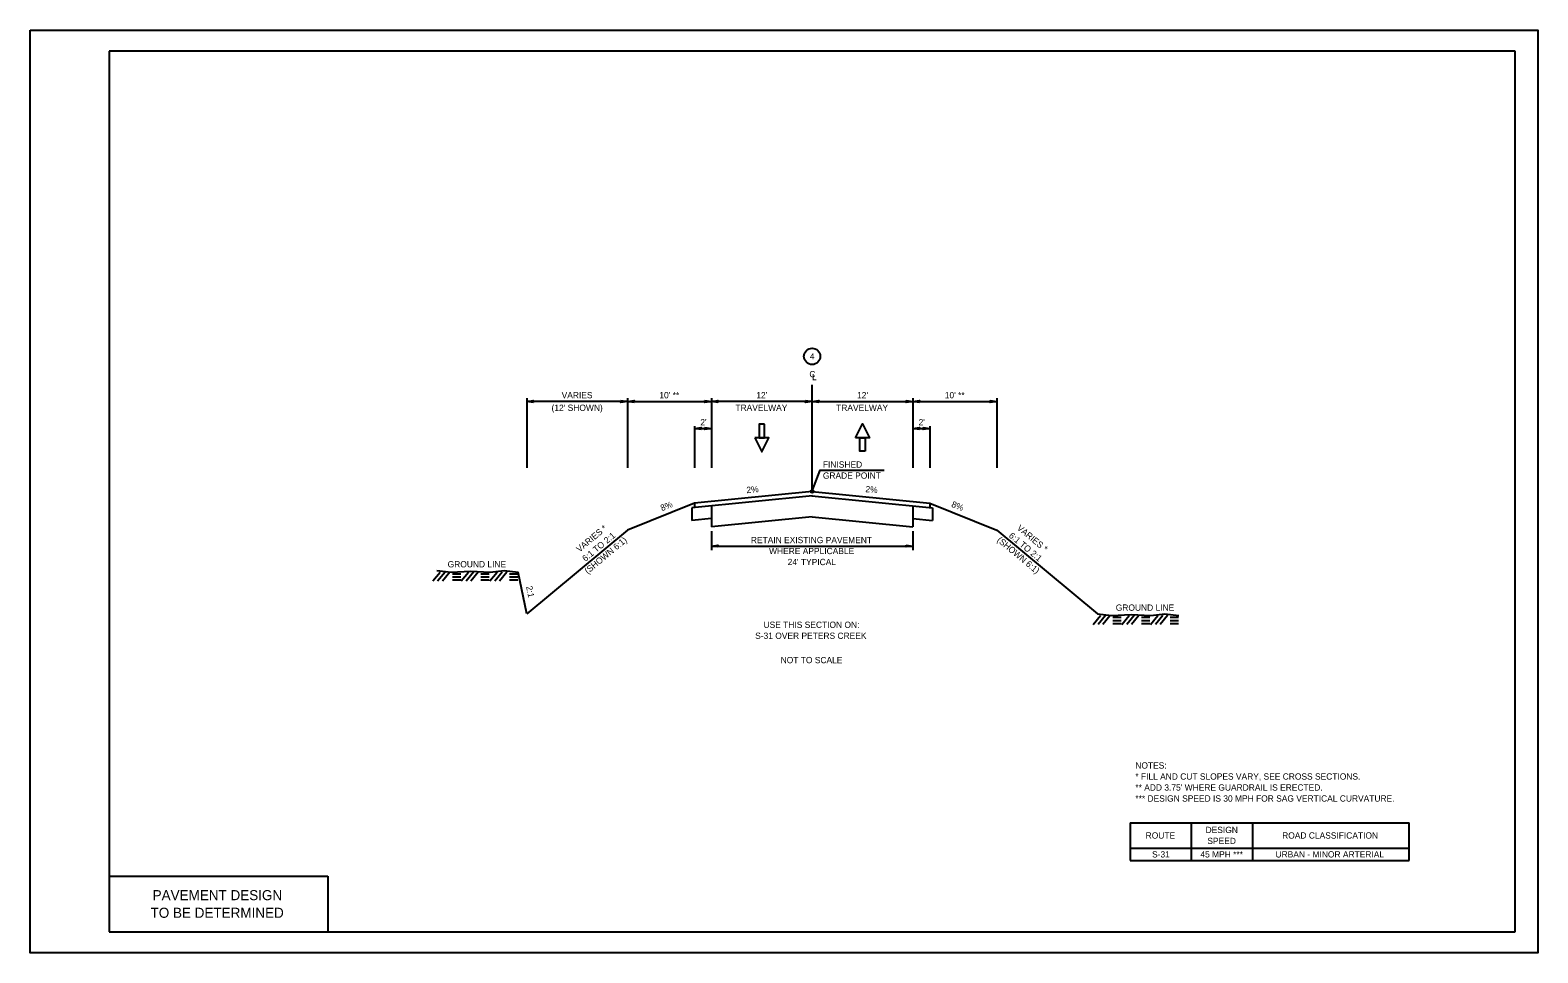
# Model space of a CAD drawing. Extents: x 1717247 to 1717427, y 1306639 to 1306749.
import ezdxf

# ---------------------------------------------------------------- set-up
doc = ezdxf.new("R2010")
doc.units = 0
for name, color, linetype in [('BR_TABLE LINES', 7, 'Continuous'), ('Default', 7, 'Continuous'), ('RD_SHT_Bndy', 7, 'Continuous'), ('RD_SHT_IplotShp', 7, 'Continuous'), ('RD_SHT_TX', 7, 'Continuous'), ('RD_SHT_Typical', 7, 'Continuous'), ('RD_TX_Misc1', 7, 'Continuous')]:
    doc.layers.add(name, color=color, linetype=linetype)

# ---------------------------------------------------------------- blocks, each defined once
blk = doc.blocks.new('ARROW2')
at = {"layer": 'Default'}
blk.add_lwpolyline([(-0.156, 0.023), (0, 0), (-0.156, -0.023)], close=True, dxfattribs=at)
blk = doc.blocks.new('LANE ARROW')
at = {"layer": 'BR_TABLE LINES'}
for points in [[(-0.328, -0.031), (-0.328, 0.031), (-0.167, 0.031), (-0.167, -0.031)], [(-0.167, 0.083), (0, 0), (-0.167, -0.083)]]:
    blk.add_lwpolyline(points, close=True, dxfattribs=at)
blk = doc.blocks.new('GROUND')
at = {"layer": 'Default'}
for p, q in [((-0.71, 0.5), (-1.59, -0.55)), ((-0.12, 0.53), (-1, -0.53)), ((0.44, 0.53), (-0.44, -0.53)), ((0.76, 0.33), (1.76, 0.33)), ((0.76, -0.03), (1.76, -0.03)), ((0.76, -0.39), (1.76, -0.39))]:
    blk.add_line(p, q, dxfattribs=at)

msp = doc.modelspace()

# ---------------------------------------------------------------- linework, layer by layer
at = {"layer": 'RD_SHT_Bndy'}
for p, q in [((1717256.56, 1306746.43), (1717256.56, 1306641.43)), ((1717424.06, 1306746.43), (1717256.56, 1306746.43)), ((1717424.06, 1306641.43), (1717424.06, 1306746.43)), ((1717256.56, 1306641.43), (1717424.06, 1306641.43))]:
    msp.add_line(p, q, dxfattribs=at)
at = {"layer": 'RD_SHT_IplotShp'}
msp.add_lwpolyline([(1717247.16, 1306748.93), (1717426.76, 1306748.93), (1717426.76, 1306638.93), (1717247.16, 1306638.93)], close=True, dxfattribs=at)
at = {"layer": 'RD_SHT_TX'}
for p, q in [((1717378.21, 1306654.43), (1717378.21, 1306649.93)), ((1717378.21, 1306654.43), (1717411.42, 1306654.43)), ((1717385.46, 1306654.43), (1717385.46, 1306649.93)), ((1717392.79, 1306649.93), (1717392.79, 1306654.43)), ((1717411.42, 1306649.93), (1717411.42, 1306654.43)), ((1717378.21, 1306651.43), (1717411.42, 1306651.43)), ((1717378.21, 1306649.93), (1717411.42, 1306649.93)), ((1717256.56, 1306648.09), (1717282.61, 1306648.09)), ((1717282.61, 1306648.09), (1717282.61, 1306641.43))]:
    msp.add_line(p, q, dxfattribs=at)
msp.add_lwpolyline([(1717340.36, 1306694.07), (1717341.27, 1306696.48), (1717348.89, 1306696.48)], dxfattribs=at)
for centre, radius in [((1717340.31, 1306710.04), 0.973), ((1717340.31, 1306693.93), 0.15)]:
    msp.add_circle(centre, radius, dxfattribs=at)
at = {"layer": 'RD_SHT_Typical'}
for p, q in [((1717326.31, 1306692.53), (1717318.31, 1306689.33)), ((1717340.36, 1306693.43), (1717325.96, 1306691.99)), ((1717340.31, 1306693.93), (1717326.31, 1306692.53)), ((1717326.31, 1306692.54), (1717326.31, 1306692.03)), ((1717340.26, 1306693.43), (1717354.66, 1306691.99)), ((1717340.31, 1306693.93), (1717354.31, 1306692.53)), ((1717354.31, 1306692.54), (1717354.31, 1306692.03)), ((1717354.31, 1306692.53), (1717362.31, 1306689.33)), ((1717325.96, 1306692), (1717325.96, 1306690.49)), ((1717328.31, 1306690.73), (1717325.96, 1306690.49)), ((1717328.31, 1306692.23), (1717328.31, 1306689.71)), ((1717340.31, 1306690.91), (1717328.31, 1306689.71)), ((1717340.31, 1306690.91), (1717352.31, 1306689.71)), ((1717352.31, 1306692.23), (1717352.31, 1306689.71)), ((1717352.31, 1306690.73), (1717354.66, 1306690.49)), ((1717354.66, 1306692), (1717354.66, 1306690.49)), ((1717318.31, 1306689.33), (1717306.31, 1306679.33)), ((1717362.31, 1306689.33), (1717374.31, 1306679.33)), ((1717306.31, 1306679.33), (1717305.31, 1306684.33))]:
    msp.add_line(p, q, dxfattribs=at)
for points in [[(1717295.62, 1306684.5), (1717297.29, 1306684.33), (1717299.63, 1306684.44), (1717301.97, 1306684.33), (1717303.64, 1306684.5), (1717305.31, 1306684.33)], [(1717374.31, 1306679.33), (1717375.98, 1306679.16), (1717378.32, 1306679.27), (1717380.66, 1306679.16), (1717382.33, 1306679.33), (1717384, 1306679.16)]]:
    msp.add_lwpolyline(points, dxfattribs=at)
at = {"layer": 'RD_TX_Misc1'}
for p, q in [((1717306.31, 1306705.07), (1717306.31, 1306696.74)), ((1717318.31, 1306705.07), (1717318.31, 1306696.74)), ((1717328.31, 1306705.07), (1717328.31, 1306696.74)), ((1717340.31, 1306693.93), (1717340.31, 1306706.64)), ((1717352.31, 1306705.07), (1717352.31, 1306696.74)), ((1717362.31, 1306705.07), (1717362.31, 1306696.74)), ((1717318.31, 1306704.67), (1717306.31, 1306704.67)), ((1717318.31, 1306704.67), (1717328.31, 1306704.67)), ((1717340.31, 1306704.67), (1717328.31, 1306704.67)), ((1717340.31, 1306704.67), (1717352.31, 1306704.67)), ((1717352.31, 1306704.67), (1717362.31, 1306704.67)), ((1717326.31, 1306701.72), (1717326.31, 1306696.74)), ((1717326.31, 1306701.44), (1717328.31, 1306701.44)), ((1717352.31, 1306701.44), (1717354.31, 1306701.44)), ((1717354.31, 1306701.72), (1717354.31, 1306696.74)), ((1717328.31, 1306689.21), (1717328.31, 1306686.93)), ((1717352.31, 1306689.21), (1717352.31, 1306686.93)), ((1717328.31, 1306687.43), (1717352.31, 1306687.43))]:
    msp.add_line(p, q, dxfattribs=at)

# ---------------------------------------------------------------- block references
at = {"layer": 'RD_SHT_Typical'}
for p in [(1717296.7, 1306683.78), (1717300.09, 1306683.78), (1717303.51, 1306683.78), (1717375.38, 1306678.6), (1717378.78, 1306678.6), (1717382.2, 1306678.6)]:
    msp.add_blockref('GROUND', p, dxfattribs=at)
at = {"layer": 'RD_TX_Misc1'}
for name, p, xscale, yscale, rotation in [('ARROW2', (1717306.31, 1306704.67), 5, 5, 180), ('ARROW2', (1717318.31, 1306704.67), 5, 5, 180), ('ARROW2', (1717328.31, 1306704.67), 5, 5, 180), ('ARROW2', (1717340.31, 1306704.67), 5, 5, 180), ('ARROW2', (1717352.31, 1306704.67), 5, 5, 180), ('ARROW2', (1717326.31, 1306701.44), 5, 5, 180), ('LANE ARROW', (1717334.31, 1306698.67), 10, -10.000000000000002, -90.00170701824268), ('LANE ARROW', (1717346.31, 1306702), 10, 10.000000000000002, 90.00170701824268), ('ARROW2', (1717352.31, 1306701.44), 5, 5, 180), ('ARROW2', (1717328.31, 1306687.43), 5, 5, 180)]:
    msp.add_blockref(name, p, dxfattribs=dict(at, xscale=xscale, yscale=yscale, rotation=rotation))
at = {"layer": 'RD_TX_Misc1', "xscale": 5, "yscale": 5}
for p in [(1717318.31, 1306704.67), (1717328.31, 1306704.67), (1717340.31, 1306704.67), (1717352.31, 1306704.67), (1717362.31, 1306704.67), (1717328.31, 1306701.44), (1717354.31, 1306701.44), (1717352.31, 1306687.43)]:
    msp.add_blockref('ARROW2', p, dxfattribs=at)

# ---------------------------------------------------------------- texts
at = {"layer": 'RD_SHT_TX'}
for s, height, p in [('4', 0.75, (1717340.04, 1306709.67)), ('GRADE POINT', 0.75, (1717341.59, 1306695.45)), ('FINISHED', 0.75, (1717341.59, 1306696.77)), ('RETAIN EXISTING PAVEMENT ', 0.75, (1717333.01, 1306687.77)), ('WHERE APPLICABLE', 0.75, (1717335.18, 1306686.46)), ('GROUND LINE', 0.75, (1717296.89, 1306684.88)), ("24' TYPICAL", 0.75, (1717337.39, 1306685.15)), ('GROUND LINE', 0.75, (1717376.48, 1306679.71)), ('USE THIS SECTION ON:', 0.75, (1717334.52, 1306677.67)), ('S-31 OVER PETERS CREEK', 0.75, (1717333.52, 1306676.36)), ('NOT TO SCALE', 0.75, (1717336.56, 1306673.46)), ('* FILL AND CUT SLOPES VARY, SEE CROSS SECTIONS.', 0.75, (1717378.81, 1306659.58)), ('NOTES:', 0.75, (1717378.81, 1306660.9)), ("** ADD 3.75' WHERE GUARDRAIL IS ERECTED.", 0.75, (1717378.81, 1306658.27)), ('*** DESIGN SPEED IS 30 MPH FOR SAG VERTICAL CURVATURE.', 0.75, (1717378.81, 1306656.96)), ('ROUTE', 0.75, (1717380.04, 1306652.55)), ('DESIGN ', 0.75, (1717387.18, 1306653.21)), ('ROAD CLASSIFICATION', 0.75, (1717396.3, 1306652.55)), ('S-31', 0.75, (1717380.8, 1306650.3)), ('SPEED', 0.75, (1717387.39, 1306651.9)), ('URBAN - MINOR ARTERIAL', 0.75, (1717395.51, 1306650.3)), ('45 MPH ***', 0.75, (1717386.56, 1306650.3)), ('PAVEMENT DESIGN', 1.2, (1717261.75, 1306645.21)), ('TO BE DETERMINED', 1.2, (1717261.5, 1306643.11))]:
    msp.add_text(s, height=height, dxfattribs=at).set_placement(p)
for s, rotation, p in [('2%', 5.7106, (1717332.52, 1306693.72)), ('2%', 354.2894, (1717346.63, 1306693.86)), ('8%', 21.8014, (1717322.42, 1306691.58)), ('8%', 338.1986, (1717356.83, 1306692.12)), ('VARIES *', 39.8056, (1717312.6, 1306686.64)), ('6:1 TO 2:1', 39.8056, (1717313.31, 1306685.53)), ('6:1 TO 2:1', 320.1944, (1717363.67, 1306688.56)), ('VARIES *', 320.1944, (1717364.64, 1306689.46)), ('(SHOWN 6:1)', 39.8056, (1717313.58, 1306684.05)), ('(SHOWN 6:1)', 320.1944, (1717362.26, 1306688.03)), ('2:1', 281.3099, (1717306.23, 1306682.6))]:
    msp.add_text(s, height=0.75, rotation=rotation, dxfattribs=at).set_placement(p)
at = {"layer": 'RD_TX_Misc1'}
for s, p in [('C', (1717339.98, 1306707.55)), ('L', (1717340.3, 1306707.2)), ('VARIES', (1717310.47, 1306705.04)), ("10' **", (1717322.11, 1306705.04)), ("12'", (1717333.66, 1306705.04)), ("12'", (1717345.66, 1306705.04)), ("10' **", (1717356.11, 1306705.04)), ("(12' SHOWN)", (1717309.27, 1306703.54)), ('TRAVELWAY', (1717331.17, 1306703.54)), ('TRAVELWAY', (1717343.17, 1306703.54)), ("2'", (1717326.99, 1306701.81)), ("2'", (1717352.99, 1306701.81))]:
    msp.add_text(s, height=0.75, dxfattribs=at).set_placement(p)

doc.saveas('drawing.dxf')
